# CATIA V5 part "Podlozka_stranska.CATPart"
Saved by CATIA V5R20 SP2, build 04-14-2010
Part number: Part1.1
Bounding box of the stored display mesh (mm): x -4.991 to 4.991, y -5 to 5, z 0 to 3
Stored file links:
  C:\Documents and Settings\Administrator\My Documents\Hobi_dokumenti\CAD_CNC\Clap_CATIA\Podlozka_stranska.CATPart
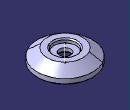
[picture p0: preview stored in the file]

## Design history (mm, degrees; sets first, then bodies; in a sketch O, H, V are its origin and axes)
StDynAnalysisRootNodeFeature1 "CATStDynAnalysisRootNodeName"
Set1
  Line1: type PtDir, RefPoint Sketch1.O, Direction Sketch1.V, Start 0, End 3
Body1 (main body)
  Sketch1 on yz-plane, origin (0, 0, 0), H (0, 1, 0), V (0, 0, 1)
    point P1 (-2, 0)
    line L1 (-2, 0) -> (-5, 0)
    line L2 (-5, 0) -> (-5, 1)
    line L3 (-2, 1) -> (-2, 0)
    point P3 (-5, 1)
    point P4 (-2, 1)
    line L4 (-2, 1) -> (-1, 1)
    point P5 (-1, 1)
    line L5 (-1, 1) -> (-1, 1.6)
    point P6 (-1, 1.6)
    line L6 (-1, 1.6) -> (-2, 1.6)
    point P7 (-2, 1.6)
    line L7 (-2, 1.6) -> (-2, 2.3)
    point P8 (-2, 2.3)
    line L8 (-2, 2.3) -> (-3.2, 2.3)
    point P9 (-3.2, 2.3)
    line L9 (-5, 1) -> (-3.2, 2.3)
    reference intersected line E1 through (0, 0) direction (-1, 0) from xy-plane
    reference intersected line E3 through (0, 0) direction (0, 1) from zx-plane
    distance V L2 = 5
    distance V L3 = 2
    distance P8 P9 = 1.2
    distance P5 P6 = 0.6
    distance P7 P8 = 0.7
    distance P6 P7 = 1
    distance P4 P1 = 1
    distance V L5 = 1
    coincidence: P1 H, P3 L4
    horizontal: L1 H, L4 H, L6 H, L8 H, E1 H
    vertical: L2 V, L3 V, L5 V, L7 V, E3 V
    perpendicularity: E1 L5
  Shaft1: profile Sketch1, axis Line1, angle 360
  Chamfer1: length 0.2, angle 45, on edge [face of Shaft1 from Sketch1.L1 | face of Shaft1 from Sketch1.L2]; edge [face of Shaft1 from Sketch1.L3 | face of Shaft1 from Sketch1.L1]; edge [face of Shaft1 from Sketch1.L8 | face of Shaft1 from Sketch1.L7]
